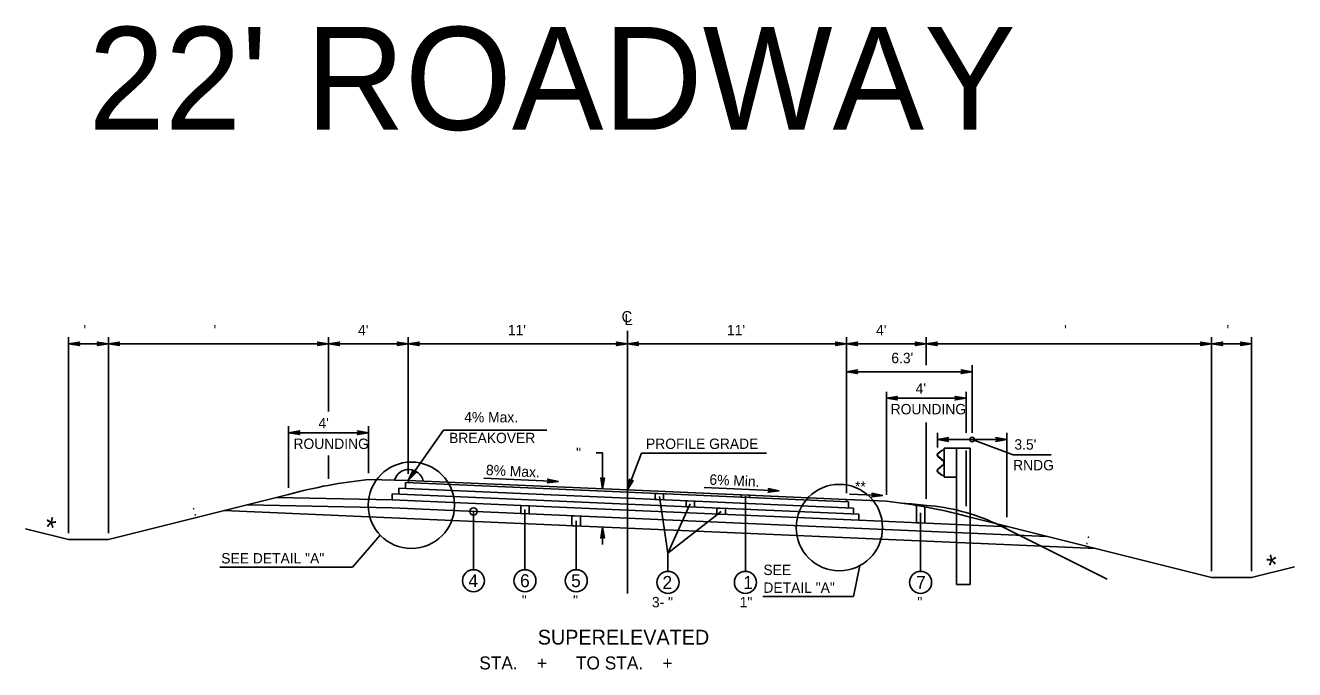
# Model space of a CAD drawing. Extents: x -540 to 1231, y -564 to 421.
# Drawn here: x 765 to 936.6, y -129.2 to -42.2 of the extents above; entities that cross this region are included whole.
import ezdxf

# ---------------------------------------------------------------- set-up
doc = ezdxf.new("R2010")
doc.units = 0
doc.layers.add('1', color=7, linetype='Continuous')
doc.layers.add('Des_ Drain_ Ftrs', color=7, linetype='Continuous')

msp = doc.modelspace()

# ---------------------------------------------------------------- linework, layer by layer
at = {"layer": '1'}
for p, q in [((846.41, -118.94), (846.41, -83.45)), ((770.84, -110.78), (770.84, -84.33)), ((776.23, -85.21), (770.84, -85.21)), ((776.23, -110.78), (776.23, -84.33)), ((806, -85.21), (776.23, -85.21)), ((806, -94.34), (806, -84.33)), ((816.78, -85.21), (806, -85.21)), ((816.78, -102.79), (816.78, -84.33)), ((846.41, -85.21), (816.78, -85.21)), ((846.41, -85.21), (876.05, -85.21)), ((876.05, -105.38), (876.05, -84.33)), ((876.05, -85.21), (886.82, -85.21)), ((886.82, -88.1), (886.82, -84.33)), ((886.82, -85.21), (925.41, -85.21)), ((925.41, -115.92), (925.41, -84.33)), ((925.41, -85.21), (930.8, -85.21)), ((930.8, -115.92), (930.8, -84.33)), ((876.05, -88.98), (893.02, -88.98)), ((893.02, -97.26), (893.02, -88.1)), ((881.43, -105.61), (881.43, -91.68)), ((881.43, -92.56), (892.21, -92.56)), ((892.21, -97.26), (892.21, -91.68)), ((886.82, -106.17), (886.82, -95.84)), ((800.61, -104.68), (800.61, -96.36)), ((811.39, -97.24), (800.61, -97.24)), ((811.39, -102.67), (811.39, -96.36)), ((816.77, -103.67), (821.55, -96.86)), ((835.5, -96.86), (821.55, -96.86)), ((888.33, -99.21), (888.33, -97.26)), ((897.71, -108.62), (897.71, -97.26)), ((888.33, -98.14), (897.71, -98.14)), ((889.24, -99.32), (889.24, -103.25)), ((889.24, -99.32), (890.93, -99.32)), ((890.93, -99.32), (890.93, -117.72)), ((892.75, -99.32), (890.93, -99.32)), ((892.75, -99.32), (892.75, -117.72)), ((893.02, -98.14), (898.58, -100.21)), ((806, -103.45), (806, -100.3)), ((843.05, -99.94), (842.17, -99.94)), ((843.05, -99.94), (843.05, -104.82)), ((846.41, -104.96), (848.32, -100.01)), ((865.24, -100.01), (848.32, -100.01)), ((888.39, -100.43), (889.13, -101.06)), ((888.93, -99.61), (888.41, -100)), ((888.41, -100.41), (889.15, -101.04)), ((888.94, -99.63), (888.43, -100.02)), ((889.24, -99.55), (888.93, -99.61)), ((889.24, -99.58), (888.94, -99.63)), ((889.21, -101.25), (889.21, -101.33)), ((889.24, -101.25), (889.24, -101.33)), ((892.21, -107.14), (892.21, -99.64)), ((898.58, -100.21), (903.73, -100.21)), ((889.13, -101.51), (888.39, -102.15)), ((889.15, -101.54), (888.41, -102.17)), ((888.41, -102.58), (888.93, -102.97)), ((888.43, -102.56), (888.94, -102.94)), ((888.94, -102.94), (889.24, -103)), ((811.39, -103.55), (816.77, -103.67)), ((846.41, -105.26), (816.43, -103.95)), ((816.43, -104.76), (816.43, -103.95)), ((846.41, -104.96), (816.77, -103.67)), ((816.77, -103.67), (816.77, -103.97)), ((826.98, -103.36), (837.09, -103.8)), ((856.81, -104.64), (866.93, -105.08)), ((888.93, -102.97), (889.24, -103.03)), ((889.24, -103.25), (890.93, -103.25)), ((800.61, -105.56), (776.23, -111.66)), ((799.02, -105.96), (814.59, -106.3)), ((846.41, -106.88), (814.59, -105.49)), ((814.59, -106.3), (814.59, -105.49)), ((814.59, -105.49), (814.59, -105.49)), ((846.41, -107.69), (814.59, -106.3)), ((846.41, -106.07), (815.51, -104.72)), ((815.51, -105.53), (815.51, -104.72)), ((876.05, -106.26), (846.41, -104.96)), ((876.29, -106.57), (846.41, -105.26)), ((876.99, -107.41), (846.41, -106.07)), ((850.74, -105.86), (851.9, -113.48)), ((862.37, -105.82), (862.37, -115.97)), ((881.43, -106.49), (876.05, -106.26)), ((876.05, -106.26), (876.05, -106.56)), ((880.96, -105.73), (876.46, -105.53)), ((846.41, -110.12), (791.91, -107.74)), ((795.05, -106.95), (814.59, -107.38)), ((846.41, -108.77), (814.59, -107.38)), ((825.6, -107.86), (825.6, -115.73)), ((832.56, -107.62), (832.56, -115.73)), ((877.69, -108.25), (846.41, -106.88)), ((877.69, -109.06), (846.41, -107.69)), ((854.92, -106.84), (851.9, -113.48)), ((859.09, -107.85), (851.9, -113.48)), ((876.29, -106.57), (876.29, -107.38)), ((876.99, -107.41), (876.99, -108.22)), ((886.05, -108.03), (886.05, -115.97)), ((888.33, -107.27), (888.33, -107.27)), ((839.49, -109.13), (839.49, -115.73)), ((876.05, -110.06), (846.41, -108.77)), ((877.69, -108.25), (877.69, -109.06)), ((877.69, -108.25), (877.69, -108.25)), ((897.97, -109.94), (877.69, -109.06)), ((892.21, -108.5), (925.41, -116.8)), ((896.21, -109.5), (911.26, -117.03)), ((765.01, -110.2), (770.84, -111.66)), ((809.25, -115.39), (812.99, -111.07)), ((843.05, -109.97), (843.05, -112.34)), ((909.73, -112.88), (846.41, -110.12)), ((903.19, -111.25), (876.05, -110.06)), ((776.23, -111.66), (770.84, -111.66)), ((851.9, -113.48), (851.9, -115.97)), ((791.32, -115.39), (809.25, -115.39)), ((877.84, -115.17), (876.96, -119.36)), ((936.63, -115.34), (930.8, -116.8)), ((892.75, -117.72), (890.93, -117.72)), ((925.41, -116.8), (930.8, -116.8)), ((864.72, -119.36), (876.96, -119.36))]:
    msp.add_line(p, q, dxfattribs=at)
for points in [[(850.17, -105.43), (851.31, -105.48), (851.31, -106.29), (850.17, -106.24)], [(861.79, -105.63), (862.94, -105.68), (862.94, -105.98), (861.79, -105.93)], [(831.99, -107.06), (833.14, -107.11), (833.14, -108.19), (831.99, -108.14)], [(854.34, -106.42), (855.49, -106.47), (855.49, -107.28), (854.34, -107.23)], [(858.52, -107.41), (859.67, -107.46), (859.67, -108.27), (858.52, -108.22)], [(885.48, -109.4), (885.48, -107.03), (886.62, -107.23), (886.62, -109.45)], [(838.92, -108.44), (840.07, -108.49), (840.07, -109.84), (838.92, -109.79)]]:
    msp.add_lwpolyline(points, close=True, dxfattribs=at)
for centre, radius in [((893.02, -98.14), 0.3), ((817.2, -107.03), 5.84), ((875.07, -110.04), 5.84), ((825.6, -107.86), 0.5), ((825.6, -117.22), 1.49), ((832.56, -117.22), 1.49), ((839.49, -117.22), 1.49), ((851.9, -117.45), 1.49), ((862.37, -117.45), 1.49), ((886.05, -117.45), 1.49)]:
    msp.add_circle(centre, radius, dxfattribs=at)
for centre, radius, start, end in [((888.58, -100.22), 0.278, 126.9799, 229.021), ((888.58, -100.22), 0.249, 126.9799, 229.021), ((888.96, -101.25), 0.249, 0, 49.0365), ((888.96, -101.25), 0.278, 0, 49.0365), ((816.85, -104.18), 2, 12.2852, 163.8102), ((888.58, -102.36), 0.278, 130.979, 233.0201), ((888.58, -102.36), 0.249, 130.979, 233.0201), ((888.96, -101.33), 0.249, 310.9635, 0), ((888.96, -101.33), 0.278, 310.9635, 0), ((818.28, -170.39), 67.19, 95.8901, 105.2487), ((874.55, -173.33), 67.19, 74.7593, 84.1179), ((876.01, -207.71), 101.24, 83.8633, 85.6775), ((884.71, -134.33), 27.37, 65.1374, 85.5513)]:
    msp.add_arc(centre, radius, start, end, dxfattribs=at)
at = {"layer": 'Des_ Drain_ Ftrs'}
for points in [[(770.84, -85.21), (772.33, -85.46), (772.03, -85.21), (772.33, -84.97)], [(776.23, -85.21), (774.74, -85.46), (775.03, -85.21), (774.74, -84.97)], [(776.23, -85.21), (777.72, -85.46), (777.42, -85.21), (777.72, -84.97)], [(806, -85.21), (804.51, -85.46), (804.81, -85.21), (804.51, -84.97)], [(806, -85.21), (807.49, -85.46), (807.19, -85.21), (807.49, -84.97)], [(816.78, -85.21), (815.29, -85.46), (815.58, -85.21), (815.29, -84.97)], [(816.78, -85.21), (818.26, -85.46), (817.97, -85.21), (818.26, -84.97)], [(846.41, -85.21), (844.92, -85.46), (845.22, -85.21), (844.92, -84.97)], [(846.41, -85.21), (847.9, -85.46), (847.6, -85.21), (847.9, -84.97)], [(876.05, -85.21), (874.56, -85.46), (874.85, -85.21), (874.56, -84.97)], [(876.05, -85.21), (877.53, -85.46), (877.24, -85.21), (877.53, -84.97)], [(886.82, -85.21), (885.33, -85.46), (885.63, -85.21), (885.33, -84.97)], [(886.82, -85.21), (888.31, -85.46), (888.02, -85.21), (888.31, -84.97)], [(925.41, -85.21), (923.92, -85.46), (924.22, -85.21), (923.92, -84.97)], [(925.41, -85.21), (926.9, -85.46), (926.6, -85.21), (926.9, -84.97)], [(930.8, -85.21), (929.31, -85.46), (929.6, -85.21), (929.31, -84.97)], [(876.05, -88.98), (877.54, -89.23), (877.24, -88.98), (877.54, -88.73)], [(893.02, -88.98), (891.53, -89.23), (891.83, -88.98), (891.53, -88.73)], [(881.43, -92.56), (882.92, -92.8), (882.63, -92.56), (882.92, -92.31)], [(892.21, -92.56), (890.72, -92.8), (891.02, -92.56), (890.72, -92.31)], [(800.61, -97.24), (802.1, -97.48), (801.8, -97.24), (802.1, -96.99)], [(811.39, -97.24), (809.9, -97.48), (810.19, -97.24), (809.9, -96.99)], [(888.33, -98.14), (889.82, -98.39), (889.52, -98.14), (889.82, -97.89)], [(897.71, -98.14), (896.22, -98.39), (896.52, -98.14), (896.22, -97.89)], [(816.77, -103.67), (817.83, -102.59), (817.46, -102.69), (817.42, -102.31)], [(837.09, -103.8), (835.59, -103.98), (835.9, -103.75), (835.62, -103.49)], [(843.05, -104.82), (843.3, -103.33), (843.05, -103.62), (842.8, -103.33)], [(846.41, -104.96), (847.18, -103.66), (846.84, -103.85), (846.71, -103.48)], [(866.93, -105.08), (865.43, -105.27), (865.73, -105.03), (865.45, -104.77)], [(880.96, -105.73), (879.46, -105.91), (879.77, -105.67), (879.48, -105.41)], [(843.05, -109.97), (843.3, -111.46), (843.05, -111.16), (842.8, -111.46)]]:
    msp.add_lwpolyline(points, close=True, dxfattribs=at)

# ---------------------------------------------------------------- texts
at = {"layer": '1'}
for s, height, p in [("22' ROADWAY", 13.8979, (773.52, -56.3)), (" '", 1.4, (772.34, -84.06)), ("  '", 1.4, (789.42, -84.06)), ("4'", 1.4, (810, -84.06)), ("11'", 1.4, (830.25, -84.06)), ("11'", 1.4, (859.88, -84.06)), ("4'", 1.4, (880.04, -84.06)), ("  '", 1.4, (904.42, -84.06)), (" '", 1.4, (926.91, -84.06)), ("6.3'", 1.4, (882.1, -87.83)), ("4'", 1.4, (885.39, -91.94)), ('ROUNDING', 1.4, (882.01, -94.74)), ("4'", 1.4, (804.65, -96.62)), ('4% Max.', 1.4, (824.35, -95.83)), ('BREAKOVER', 1.4, (822.3, -98.63)), ('ROUNDING', 1.4, (801.26, -99.42)), ('PROFILE GRADE', 1.4, (848.93, -99.42)), ("3.5'", 1.4, (898.74, -99.51)), ('RNDG', 1.4, (898.57, -102.31)), ('SEE DETAIL "A"', 1.4, (791.5, -114.89)), ('4', 1.75, (824.92, -118.09)), ('6', 1.75, (831.9, -118.09)), ('5', 1.75, (838.8, -118.09)), ('2', 1.75, (851.16, -118.33)), ('1', 1.75, (862.07, -118.33)), ('SEE', 1.4, (864.8, -116.46)), ('7', 1.75, (885.45, -118.33)), ('DETAIL "A"', 1.4, (864.8, -118.86)), (' "', 1.4, (831.62, -120.58)), (' "', 1.4, (838.55, -120.58)), ('3- "', 1.4, (849.73, -120.81)), ('1"', 1.4, (861.6, -120.81)), (' "', 1.4, (885.1, -120.81)), ('SUPERELEVATED', 2, (834.29, -125.85)), ('STA.    +      TO STA.    +     ', 1.75, (826.38, -129.21))]:
    msp.add_text(s, height=height, dxfattribs=at).set_placement(p)
for s, height, rotation, p in [('  "', 1.4, 0.1438, (838.44, -100.64)), ('8% Max.', 1.4, 357.376, (827.26, -102.94)), ('6% Min.', 1.4, 357.3732, (857.48, -104.24)), ('**', 1.4, 357.2164, (877.14, -105.16)), (' : ', 1.4, 14.2282, (787.24, -108.62)), ('*', 2.8, 347.1521, (767.33, -111.22)), (' : ', 1.4, 345.7718, (907.76, -112.1)), ('*', 2.8, 12.8479, (933.26, -116.61))]:
    msp.add_text(s, height=height, rotation=rotation, dxfattribs=at).set_placement(p)
at = {"layer": 'Des_ Drain_ Ftrs'}
for s, p in [('C', (845.62, -82.29)), ('L', (846.01, -82.69))]:
    msp.add_text(s, height=1.5, dxfattribs=at).set_placement(p)

doc.saveas('drawing.dxf')
